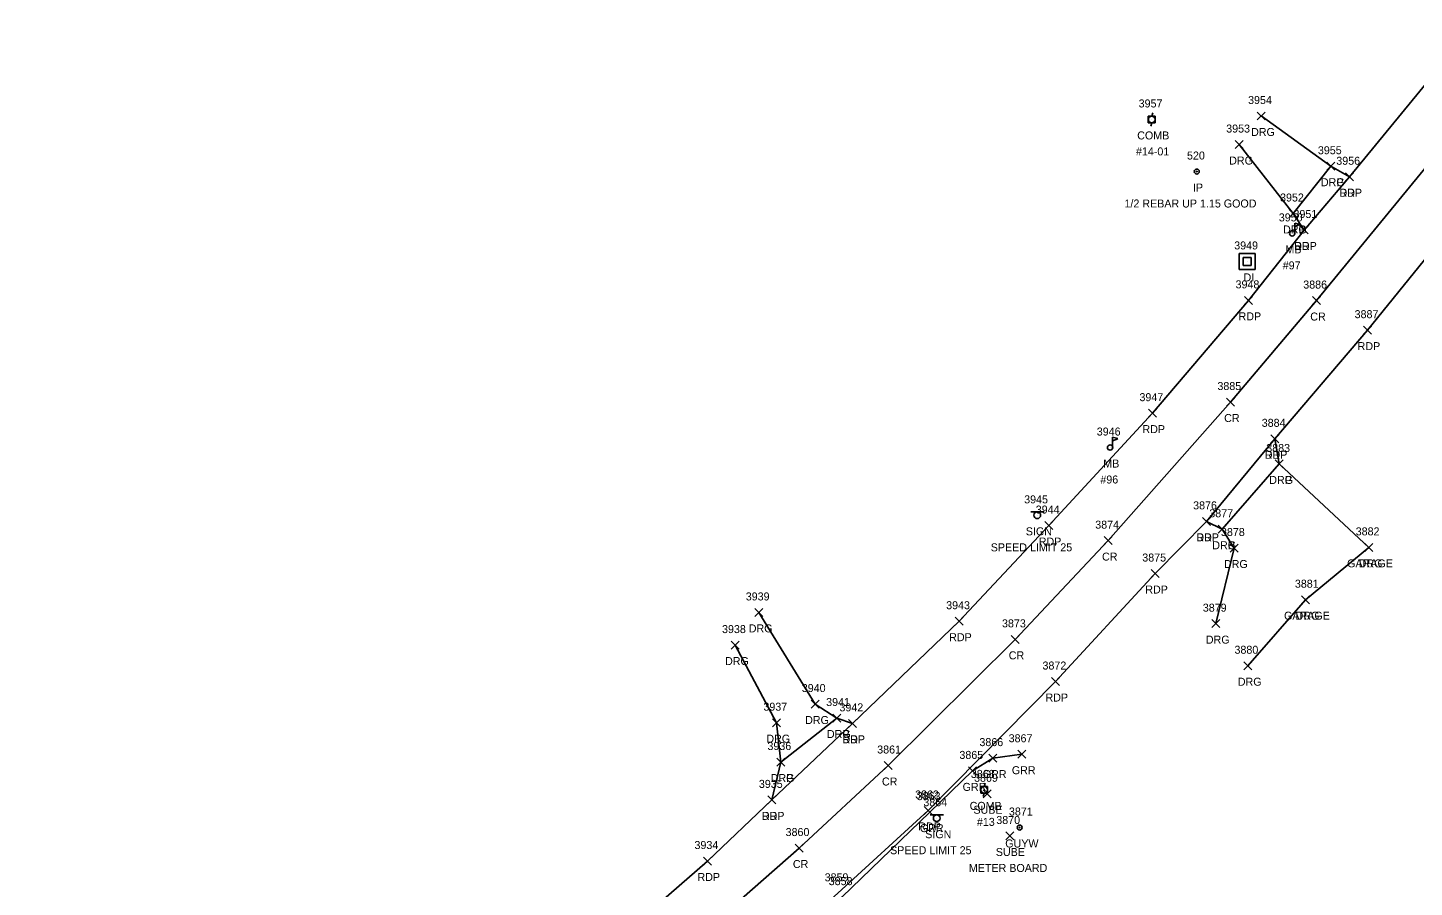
# Model space of a CAD drawing. Extents: x 1690689 to 1696275, y 438760 to 444007.
# Drawn here: x 1692261 to 1692607.6, y 442765.1 to 442980.1 of the extents above; entities that cross this region are included whole.
import ezdxf

# ---------------------------------------------------------------- set-up
doc = ezdxf.new("R2010")
doc.units = 0
for name, color, linetype in [('D_A', 7, 'Continuous'), ('D_I', 7, 'Continuous'), ('DS', 7, 'Continuous'), ('L_A', 7, 'Continuous'), ('L_C', 7, 'Continuous'), ('L_I', 7, 'Continuous'), ('L_TIC', 7, 'Continuous'), ('LBC', 7, 'Continuous'), ('LMB', 7, 'Continuous'), ('M_A', 7, 'Continuous'), ('M_C', 7, 'Continuous'), ('M_I', 7, 'Continuous'), ('MPIR', 7, 'Continuous'), ('P_A', 7, 'Continuous'), ('P_I', 7, 'Continuous'), ('P_TIC', 7, 'Continuous'), ('PET', 7, 'Continuous'), ('PRC', 7, 'Continuous'), ('R_A', 7, 'Continuous'), ('R_I', 7, 'Continuous'), ('R_TIC', 7, 'Continuous'), ('RDG', 7, 'Continuous'), ('RDP', 7, 'Continuous'), ('RGR', 7, 'Continuous'), ('S_A', 7, 'Continuous'), ('S_C', 7, 'Continuous'), ('S_I', 7, 'Continuous'), ('SSGN', 7, 'Continuous'), ('U_A', 7, 'Continuous'), ('U_C', 7, 'Continuous'), ('U_I', 7, 'Continuous'), ('U_TIC', 7, 'Continuous'), ('UP', 7, 'Continuous'), ('UPGW', 7, 'Continuous')]:
    doc.layers.add(name, color=color, linetype=linetype)

msp = doc.modelspace()

# ---------------------------------------------------------------- linework, layer by layer
at = {"layer": 'DS'}
for p, q in [((1692563.9, 442923.63), (1692567.9, 442923.63)), ((1692563.9, 442919.63), (1692563.9, 442923.63)), ((1692564.9, 442920.63), (1692564.9, 442922.63)), ((1692564.9, 442922.63), (1692566.9, 442922.63)), ((1692566.9, 442922.63), (1692566.9, 442920.63)), ((1692567.9, 442923.63), (1692567.9, 442919.63)), ((1692567.9, 442919.63), (1692563.9, 442919.63)), ((1692566.9, 442920.63), (1692564.9, 442920.63)), ((1692565.9, 442921.63), (1692565.9, 442921.63)), ((1692565.9, 442921.63), (1692565.9, 442921.63))]:
    msp.add_line(p, q, dxfattribs=at)
at = {"layer": 'L_TIC'}
for points in [[(1692595.26, 442849.09), (1692597.26, 442851.09)], [(1692597.26, 442849.09), (1692595.26, 442851.09)], [(1692579.49, 442836), (1692581.49, 442838)], [(1692581.49, 442836), (1692579.49, 442838)]]:
    msp.add_lwpolyline(points, dxfattribs=at)
at = {"layer": 'LBC'}
msp.add_lwpolyline([(1692580.49, 442837), (1692596.26, 442850.09)], dxfattribs=at)
at = {"layer": 'LMB'}
for p, q in [((1692577.77, 442931.24), (1692579.07, 442930.86)), ((1692577.78, 442928.65), (1692577.78, 442931.24)), ((1692577.78, 442930.34), (1692579.06, 442930.85)), ((1692577.12, 442928.64), (1692577.12, 442928.64)), ((1692532.24, 442875.08), (1692532.24, 442877.68)), ((1692532.24, 442877.67), (1692533.53, 442877.29)), ((1692532.24, 442876.78), (1692533.53, 442877.28)), ((1692531.59, 442875.07), (1692531.59, 442875.07))]:
    msp.add_line(p, q, dxfattribs=at)
for centre in [(1692577.12, 442928.64), (1692531.59, 442875.07)]:
    msp.add_circle(centre, 0.656, dxfattribs=at)
at = {"layer": 'MPIR'}
for radius in [0.625, 0.0833]:
    msp.add_circle((1692553.27, 442944.12), radius, dxfattribs=at)
at = {"layer": 'P_TIC'}
for points in [[(1692590.46, 442941.81), (1692592.46, 442943.81)], [(1692592.46, 442941.81), (1692590.46, 442943.81)], [(1692579.14, 442928.49), (1692581.14, 442930.49)], [(1692581.14, 442928.49), (1692579.14, 442930.49)], [(1692565.23, 442910.89), (1692567.23, 442912.89)], [(1692567.23, 442910.89), (1692565.23, 442912.89)], [(1692582.2, 442910.84), (1692584.2, 442912.84)], [(1692584.2, 442910.84), (1692582.2, 442912.84)], [(1692594.99, 442903.43), (1692596.99, 442905.43)], [(1692596.99, 442903.43), (1692594.99, 442905.43)], [(1692560.69, 442885.45), (1692562.69, 442887.45)], [(1692562.69, 442885.45), (1692560.69, 442887.45)], [(1692541.2, 442882.67), (1692543.2, 442884.67)], [(1692543.2, 442882.67), (1692541.2, 442884.67)], [(1692571.77, 442876.25), (1692573.77, 442878.25)], [(1692573.77, 442876.25), (1692571.77, 442878.25)], [(1692515.27, 442854.55), (1692517.27, 442856.55)], [(1692517.27, 442854.55), (1692515.27, 442856.55)], [(1692554.67, 442855.6), (1692556.67, 442857.6)], [(1692556.67, 442855.6), (1692554.67, 442857.6)], [(1692530.15, 442850.78), (1692532.15, 442852.78)], [(1692532.15, 442850.78), (1692530.15, 442852.78)], [(1692541.91, 442842.55), (1692543.91, 442844.55)], [(1692543.91, 442842.55), (1692541.91, 442844.55)], [(1692492.88, 442830.62), (1692494.88, 442832.62)], [(1692494.88, 442830.62), (1692492.88, 442832.62)], [(1692506.84, 442826.08), (1692508.84, 442828.08)], [(1692508.84, 442826.08), (1692506.84, 442828.08)], [(1692516.96, 442815.53), (1692518.96, 442817.53)], [(1692518.96, 442815.53), (1692516.96, 442817.53)], [(1692466.2, 442805.07), (1692468.2, 442807.07)], [(1692468.2, 442805.07), (1692466.2, 442807.07)], [(1692475.12, 442794.52), (1692477.12, 442796.52)], [(1692477.12, 442794.52), (1692475.12, 442796.52)], [(1692446.06, 442785.92), (1692448.06, 442787.92)], [(1692448.06, 442785.92), (1692446.06, 442787.92)], [(1692485.16, 442783.27), (1692487.16, 442785.27)], [(1692487.16, 442783.27), (1692485.16, 442785.27)], [(1692452.87, 442773.87), (1692454.87, 442775.87)], [(1692454.87, 442773.87), (1692452.87, 442775.87)], [(1692429.96, 442770.62), (1692431.96, 442772.62)], [(1692431.96, 442770.62), (1692429.96, 442772.62)]]:
    msp.add_lwpolyline(points, dxfattribs=at)
at = {"layer": 'PET'}
for points in [[(1692237.88, 442639.6), (1692264.12, 442652.5), (1692286.22, 442664.61), (1692319.2, 442685.32), (1692347.67, 442704.38), (1692374.05, 442724.48), (1692407.15, 442750.82), (1692430.96, 442771.62), (1692447.06, 442786.92), (1692467.2, 442806.07), (1692493.88, 442831.62), (1692516.27, 442855.55), (1692542.2, 442883.67), (1692566.23, 442911.89), (1692580.14, 442929.49), (1692591.46, 442942.81), (1692622.03, 442980.1)], [(1692249.14, 442615.42), (1692279.05, 442629.91), (1692314.53, 442648.72), (1692338.29, 442663.91), (1692352.76, 442674.35), (1692382.73, 442695.76), (1692404.39, 442712.64), (1692438.92, 442741.2), (1692463.5, 442763.55), (1692486.16, 442784.27), (1692517.96, 442816.53), (1692542.91, 442843.55), (1692555.67, 442856.6), (1692572.77, 442877.25), (1692595.99, 442904.43), (1692626.93, 442942.69)]]:
    msp.add_lwpolyline(points, dxfattribs=at)
at = {"layer": 'PRC'}
msp.add_lwpolyline([(1691980.06, 442550.02), (1692039.61, 442563.23), (1692083.25, 442573.72), (1692116.57, 442582.24), (1692147.26, 442591.19), (1692177.12, 442600.79), (1692208.36, 442612.46), (1692243, 442627.71), (1692273.4, 442642.72), (1692303.11, 442659.56), (1692344.15, 442686.64), (1692371.8, 442706.74), (1692395.14, 442724.9), (1692427.8, 442751.94), (1692453.87, 442774.87), (1692476.12, 442795.52), (1692507.84, 442827.08), (1692531.15, 442851.78), (1692561.69, 442886.45), (1692583.2, 442911.84), (1692616.35, 442952.3)], dxfattribs=at)
at = {"layer": 'R_TIC'}
for points in [[(1692568.36, 442957.01), (1692570.36, 442959.01)], [(1692570.36, 442957.01), (1692568.36, 442959.01)], [(1692562.89, 442949.87), (1692564.89, 442951.87)], [(1692564.89, 442949.87), (1692562.89, 442951.87)], [(1692585.81, 442944.44), (1692587.81, 442946.44)], [(1692587.81, 442944.44), (1692585.81, 442946.44)], [(1692585.81, 442944.44), (1692587.81, 442946.44)], [(1692587.81, 442944.44), (1692585.81, 442946.44)], [(1692590.46, 442941.81), (1692592.46, 442943.81)], [(1692592.46, 442941.81), (1692590.46, 442943.81)], [(1692576.35, 442932.62), (1692578.35, 442934.62)], [(1692578.35, 442932.62), (1692576.35, 442934.62)], [(1692576.35, 442932.62), (1692578.35, 442934.62)], [(1692578.35, 442932.62), (1692576.35, 442934.62)], [(1692579.14, 442928.49), (1692581.14, 442930.49)], [(1692581.14, 442928.49), (1692579.14, 442930.49)], [(1692571.77, 442876.25), (1692573.77, 442878.25)], [(1692573.77, 442876.25), (1692571.77, 442878.25)], [(1692572.9, 442869.96), (1692574.9, 442871.96)], [(1692574.9, 442869.96), (1692572.9, 442871.96)], [(1692572.9, 442869.96), (1692574.9, 442871.96)], [(1692574.9, 442869.96), (1692572.9, 442871.96)], [(1692554.67, 442855.6), (1692556.67, 442857.6)], [(1692556.67, 442855.6), (1692554.67, 442857.6)], [(1692558.66, 442853.62), (1692560.66, 442855.62)], [(1692560.66, 442853.62), (1692558.66, 442855.62)], [(1692558.66, 442853.62), (1692560.66, 442855.62)], [(1692560.66, 442853.62), (1692558.66, 442855.62)], [(1692561.58, 442848.93), (1692563.58, 442850.93)], [(1692563.58, 442848.93), (1692561.58, 442850.93)], [(1692595.26, 442849.09), (1692597.26, 442851.09)], [(1692597.26, 442849.09), (1692595.26, 442851.09)], [(1692579.49, 442836), (1692581.49, 442838)], [(1692581.49, 442836), (1692579.49, 442838)], [(1692442.78, 442832.82), (1692444.78, 442834.82)], [(1692444.78, 442832.82), (1692442.78, 442834.82)], [(1692557.05, 442830.01), (1692559.05, 442832.01)], [(1692559.05, 442830.01), (1692557.05, 442832.01)], [(1692436.85, 442824.65), (1692438.85, 442826.65)], [(1692438.85, 442824.65), (1692436.85, 442826.65)], [(1692565.04, 442819.48), (1692567.04, 442821.48)], [(1692567.04, 442819.48), (1692565.04, 442821.48)], [(1692456.88, 442809.9), (1692458.88, 442811.9)], [(1692458.88, 442809.9), (1692456.88, 442811.9)], [(1692462.31, 442806.4), (1692464.31, 442808.4)], [(1692464.31, 442806.4), (1692462.31, 442808.4)], [(1692462.31, 442806.4), (1692464.31, 442808.4)], [(1692464.31, 442806.4), (1692462.31, 442808.4)], [(1692447.19, 442805.23), (1692449.19, 442807.23)], [(1692449.19, 442805.23), (1692447.19, 442807.23)], [(1692466.2, 442805.07), (1692468.2, 442807.07)], [(1692468.2, 442805.07), (1692466.2, 442807.07)], [(1692448.26, 442795.39), (1692450.26, 442797.39)], [(1692450.26, 442795.39), (1692448.26, 442797.39)], [(1692448.26, 442795.39), (1692450.26, 442797.39)], [(1692450.26, 442795.39), (1692448.26, 442797.39)], [(1692501.29, 442796.37), (1692503.29, 442798.37)], [(1692503.29, 442796.37), (1692501.29, 442798.37)], [(1692508.55, 442797.34), (1692510.55, 442799.34)], [(1692510.55, 442797.34), (1692508.55, 442799.34)], [(1692496.24, 442793.17), (1692498.24, 442795.17)], [(1692498.24, 442793.17), (1692496.24, 442795.17)], [(1692446.06, 442785.92), (1692448.06, 442787.92)], [(1692448.06, 442785.92), (1692446.06, 442787.92)], [(1692485.57, 442782.86), (1692487.57, 442784.86)], [(1692487.57, 442782.86), (1692485.57, 442784.86)]]:
    msp.add_lwpolyline(points, dxfattribs=at)
at = {"layer": 'RDG'}
for points in [[(1692569.36, 442958.01), (1692586.81, 442945.44)], [(1692577.35, 442933.62), (1692563.89, 442950.87)], [(1692596.26, 442850.09), (1692573.9, 442870.96)], [(1692559.66, 442854.62), (1692562.58, 442849.93), (1692558.05, 442831.01)], [(1692566.04, 442820.48), (1692580.49, 442837)], [(1692443.78, 442833.82), (1692457.88, 442810.9), (1692463.31, 442807.4)], [(1692449.26, 442796.39), (1692448.19, 442806.23), (1692437.85, 442825.65)]]:
    msp.add_lwpolyline(points, dxfattribs=at)
at = {"layer": 'RDP'}
for points in [[(1692580.14, 442929.49), (1692577.35, 442933.62), (1692586.81, 442945.44), (1692591.46, 442942.81)], [(1692555.67, 442856.6), (1692559.66, 442854.62), (1692573.9, 442870.96), (1692572.77, 442877.25)], [(1692447.06, 442786.92), (1692449.26, 442796.39), (1692463.31, 442807.4), (1692467.2, 442806.07)]]:
    msp.add_lwpolyline(points, dxfattribs=at)
at = {"layer": 'RGR'}
msp.add_lwpolyline([(1692346.78, 442662.14), (1692348.76, 442668.75), (1692353.19, 442673.91), (1692382.85, 442695.4), (1692404.6, 442712.06), (1692439.37, 442740.65), (1692464.52, 442762.59), (1692486.57, 442783.86), (1692497.24, 442794.17), (1692502.29, 442797.37), (1692509.55, 442798.34)], dxfattribs=at)
at = {"layer": 'SSGN'}
for p, q in [((1692511.75, 442858.95), (1692515.08, 442858.95)), ((1692513.4, 442858.12), (1692513.4, 442858.12)), ((1692486.6, 442783.19), (1692489.93, 442783.19)), ((1692488.25, 442782.35), (1692488.25, 442782.35))]:
    msp.add_line(p, q, dxfattribs=at)
for centre in [(1692513.4, 442858.12), (1692488.25, 442782.35)]:
    msp.add_circle(centre, 0.833, dxfattribs=at)
at = {"layer": 'U_TIC'}
for points in [[(1692499.9, 442787.45), (1692501.9, 442789.45)], [(1692501.9, 442787.45), (1692499.9, 442789.45)], [(1692505.5, 442776.89), (1692507.5, 442778.89)], [(1692507.5, 442776.89), (1692505.5, 442778.89)]]:
    msp.add_lwpolyline(points, dxfattribs=at)
at = {"layer": 'UP'}
for p, q in [((1692541.16, 442956.31), (1692541.16, 442957.98)), ((1692541.16, 442957.98), (1692542.83, 442957.98)), ((1692542.25, 442958.81), (1692542, 442957.98)), ((1692542, 442957.15), (1692542, 442957.15)), ((1692542.83, 442957.98), (1692542.83, 442956.31)), ((1692542.83, 442956.31), (1692541.16, 442956.31)), ((1692541.75, 442955.48), (1692542, 442956.31)), ((1692500.35, 442791.09), (1692500.1, 442790.25)), ((1692499.26, 442788.59), (1692499.26, 442790.25)), ((1692499.26, 442790.25), (1692500.93, 442790.25)), ((1692500.93, 442788.59), (1692499.26, 442788.59)), ((1692499.85, 442787.75), (1692500.1, 442788.59)), ((1692500.1, 442789.42), (1692500.1, 442789.42)), ((1692500.93, 442790.25), (1692500.93, 442788.59))]:
    msp.add_line(p, q, dxfattribs=at)
for centre in [(1692542, 442957.15), (1692500.1, 442789.42)]:
    msp.add_circle(centre, 0.833, dxfattribs=at)
at = {"layer": 'UPGW'}
for radius in [0.625, 0.0833]:
    msp.add_circle((1692509, 442780.01), radius, dxfattribs=at)

# ---------------------------------------------------------------- texts
at = {"layer": 'D_A'}
msp.add_text('DI', height=2, dxfattribs=at).set_placement((1692564.96, 442916.63))
at = {"layer": 'D_I'}
msp.add_text('3949', height=2, dxfattribs=at).set_placement((1692562.63, 442924.63))
at = {"layer": 'L_A'}
for s, p in [('MB', (1692575.43, 442923.64)), ('MB', (1692529.9, 442870.07)), ('GARAGE', (1692590.86, 442845.09)), ('GARAGE', (1692575.09, 442832))]:
    msp.add_text(s, height=2, dxfattribs=at).set_placement(p)
at = {"layer": 'L_C'}
for s, p in [('#97', (1692574.76, 442919.64)), ('#96', (1692529.17, 442866.07))]:
    msp.add_text(s, height=2, dxfattribs=at).set_placement(p)
at = {"layer": 'L_I'}
for s, p in [('3950', (1692573.78, 442931.64)), ('3946', (1692528.27, 442878.07)), ('3882', (1692593, 442853.09)), ('3881', (1692577.8, 442840))]:
    msp.add_text(s, height=2, dxfattribs=at).set_placement(p)
at = {"layer": 'M_A'}
msp.add_text('IP', height=2, dxfattribs=at).set_placement((1692552.32, 442939.12))
at = {"layer": 'M_C'}
msp.add_text('1/2 REBAR UP 1.15 GOOD', height=2, dxfattribs=at).set_placement((1692535.2, 442935.12))
at = {"layer": 'M_I'}
msp.add_text('520', height=2, dxfattribs=at).set_placement((1692550.83, 442947.12))
at = {"layer": 'P_A'}
for s, p in [('RDP', (1692588.95, 442937.81)), ('RDP', (1692577.63, 442924.49)), ('RDP', (1692563.72, 442906.89)), ('CR', (1692581.64, 442906.84)), ('RDP', (1692593.48, 442899.43)), ('RDP', (1692539.69, 442878.67)), ('CR', (1692560.12, 442881.45)), ('RDP', (1692570.26, 442872.25)), ('RDP', (1692553.16, 442851.6)), ('RDP', (1692513.76, 442850.55)), ('CR', (1692529.59, 442846.78)), ('RDP', (1692540.4, 442838.55)), ('RDP', (1692491.37, 442826.62)), ('CR', (1692506.27, 442822.08)), ('RDP', (1692515.45, 442811.53)), ('RDP', (1692464.69, 442801.07)), ('CR', (1692474.56, 442790.52)), ('RDP', (1692444.55, 442781.92)), ('RDP', (1692483.65, 442779.27)), ('CR', (1692452.3, 442769.87)), ('RDP', (1692428.45, 442766.62))]:
    msp.add_text(s, height=2, dxfattribs=at).set_placement(p)
at = {"layer": 'P_I'}
for s, p in [('3956', (1692588.15, 442945.81)), ('3951', (1692577.45, 442932.49)), ('3948', (1692562.97, 442914.89)), ('3886', (1692579.89, 442914.84)), ('3887', (1692592.73, 442907.43)), ('3885', (1692558.43, 442889.45)), ('3947', (1692538.94, 442886.67)), ('3884', (1692569.51, 442880.25)), ('3944', (1692513.01, 442858.55)), ('3876', (1692552.36, 442859.6)), ('3874', (1692527.89, 442854.78)), ('3875', (1692539.65, 442846.55)), ('3943', (1692490.62, 442834.62)), ('3873', (1692504.58, 442830.08)), ('3872', (1692514.7, 442819.53)), ('3942', (1692463.94, 442809.07)), ('3861', (1692473.38, 442798.52)), ('3935', (1692443.8, 442789.92)), ('3862', (1692482.85, 442787.27)), ('3934', (1692427.7, 442774.62)), ('3860', (1692450.48, 442777.87)), ('3859', (1692460.24, 442766.55))]:
    msp.add_text(s, height=2, dxfattribs=at).set_placement(p)
at = {"layer": 'R_A'}
for s, p in [('DRG', (1692566.85, 442953.01)), ('DRG', (1692561.37, 442945.87)), ('DRG', (1692584.3, 442940.44)), ('DRP', (1692584.3, 442940.44)), ('DRP', (1692588.95, 442937.81)), ('DRG', (1692574.83, 442928.62)), ('DRP', (1692574.83, 442928.62)), ('DRP', (1692577.63, 442924.49)), ('DRP', (1692570.26, 442872.25)), ('DRG', (1692571.39, 442865.96)), ('DRP', (1692571.39, 442865.96)), ('DRP', (1692553.16, 442851.6)), ('DRG', (1692557.15, 442849.62)), ('DRP', (1692557.15, 442849.62)), ('DRG', (1692560.07, 442844.93)), ('DRG', (1692593.75, 442845.09)), ('DRG', (1692577.98, 442832)), ('DRG', (1692441.27, 442828.82)), ('DRG', (1692555.54, 442826.01)), ('DRG', (1692435.34, 442820.65)), ('DRG', (1692563.53, 442815.48)), ('DRG', (1692455.36, 442805.9)), ('DRG', (1692460.8, 442802.4)), ('DRP', (1692460.8, 442802.4)), ('DRG', (1692445.67, 442801.23)), ('DRP', (1692464.69, 442801.07)), ('GRR', (1692499.78, 442792.37)), ('GRR', (1692507.04, 442793.34)), ('DRG', (1692446.75, 442791.39)), ('DRP', (1692446.75, 442791.39)), ('GRR', (1692494.73, 442789.17)), ('DRP', (1692444.55, 442781.92)), ('GRR', (1692484.05, 442778.86))]:
    msp.add_text(s, height=2, dxfattribs=at).set_placement(p)
at = {"layer": 'R_I'}
for s, p in [('3954', (1692566.1, 442961.01)), ('3953', (1692560.63, 442953.87)), ('3955', (1692583.55, 442948.44)), ('3955', (1692583.55, 442948.44)), ('3956', (1692588.15, 442945.81)), ('3952', (1692574.09, 442936.62)), ('3952', (1692574.09, 442936.62)), ('3951', (1692577.45, 442932.49)), ('3884', (1692569.51, 442880.25)), ('3883', (1692570.64, 442873.96)), ('3883', (1692570.64, 442873.96)), ('3876', (1692552.36, 442859.6)), ('3877', (1692556.4, 442857.62)), ('3877', (1692556.4, 442857.62)), ('3878', (1692559.32, 442852.93)), ('3882', (1692593, 442853.09)), ('3881', (1692577.8, 442840)), ('3939', (1692440.52, 442836.82)), ('3879', (1692554.78, 442834.01)), ('3938', (1692434.59, 442828.65)), ('3880', (1692562.7, 442823.48)), ('3940', (1692454.53, 442813.9)), ('3937', (1692444.93, 442809.23)), ('3941', (1692460.62, 442810.4)), ('3941', (1692460.62, 442810.4)), ('3942', (1692463.94, 442809.07)), ('3936', (1692445.94, 442799.39)), ('3936', (1692445.94, 442799.39)), ('3866', (1692498.93, 442800.37)), ('3867', (1692506.24, 442801.34)), ('3865', (1692493.93, 442797.17)), ('3935', (1692443.8, 442789.92)), ('3863', (1692483.26, 442786.86)), ('3858', (1692461.26, 442765.59))]:
    msp.add_text(s, height=2, dxfattribs=at).set_placement(p)
at = {"layer": 'S_A'}
for p in [(1692510.53, 442853.1), (1692485.38, 442777.33)]:
    msp.add_text('SIGN', height=2, dxfattribs=at).set_placement(p)
at = {"layer": 'S_C'}
for p in [(1692501.76, 442849.1), (1692476.6, 442773.33)]:
    msp.add_text('SPEED LIMIT 25', height=2, dxfattribs=at).set_placement(p)
at = {"layer": 'S_I'}
for s, p in [('3945', (1692510.12, 442861.1)), ('3864', (1692484.92, 442785.33))]:
    msp.add_text(s, height=2, dxfattribs=at).set_placement(p)
at = {"layer": 'U_A'}
for s, p in [('COMB', (1692538.38, 442952.15)), ('COMB', (1692496.48, 442784.42)), ('SUBE', (1692497.44, 442783.45)), ('GUYW', (1692505.39, 442775.01)), ('SUBE', (1692503.03, 442772.89))]:
    msp.add_text(s, height=2, dxfattribs=at).set_placement(p)
at = {"layer": 'U_C'}
for s, p in [('#14-01', (1692538.07, 442948.15)), ('#13', (1692498.3, 442780.42)), ('METER BOARD', (1692496.3, 442768.89))]:
    msp.add_text(s, height=2, dxfattribs=at).set_placement(p)
at = {"layer": 'U_I'}
for s, p in [('3957', (1692538.74, 442960.15)), ('3868', (1692496.79, 442792.42)), ('3869', (1692497.59, 442791.45)), ('3871', (1692506.31, 442783.01)), ('3870', (1692503.15, 442780.89))]:
    msp.add_text(s, height=2, dxfattribs=at).set_placement(p)

doc.saveas('drawing.dxf')
